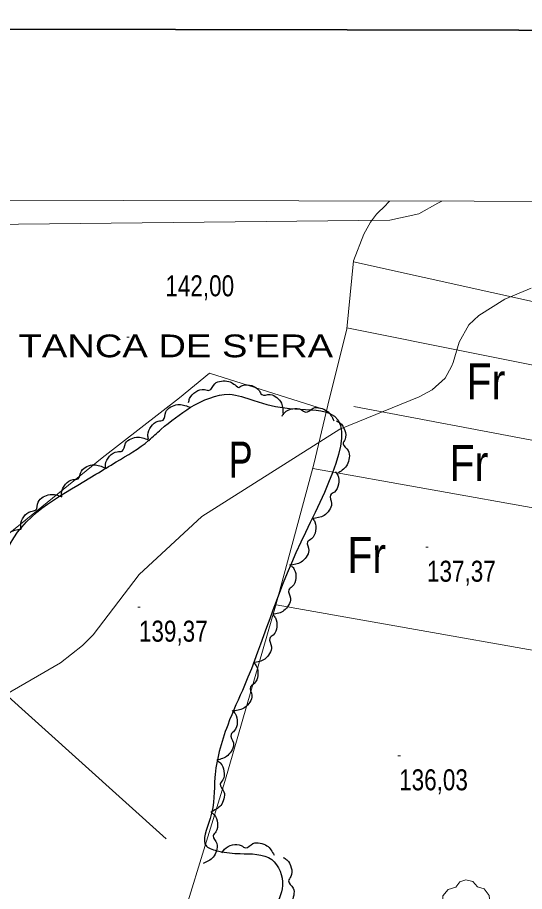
# Model space of a CAD drawing. Extents: x 483843 to 488449, y 4381269 to 4384483.
# Drawn here: x 486538.8 to 486749.9, y 4383843 to 4384207.4 of the extents above; entities that cross this region are included whole.
import ezdxf
from ezdxf.enums import TextEntityAlignment as Align

# ---------------------------------------------------------------- set-up
doc = ezdxf.new("R2010")
doc.units = 0
doc.header["$LTSCALE"] = 3.8
for name, color, linetype, lineweight in [('1', 7, 'Continuous', 13), ('27', 7, 'Continuous', 25), ('29', 7, 'Continuous', 13), ('51', 7, 'Continuous', 13), ('7', 7, 'Continuous', 13), ('9', 7, 'Continuous', 13)]:
    doc.layers.add(name, color=color, linetype=linetype, lineweight=lineweight)
doc.layers.add('31', color=7, linetype='Continuous')
doc.layers.add('5', color=7, linetype='Continuous')

msp = doc.modelspace()

# ---------------------------------------------------------------- linework, layer by layer
at = {"layer": '1', "lineweight": 35}
msp.add_lwpolyline([(484030.2, 4384207.38), (487748.7, 4384200.21), (487743.96, 4381745.22), (484025.46, 4381752.39)], close=True, dxfattribs=at)
at = {"layer": '1'}
msp.add_lwpolyline([(484100.5, 4384135.8), (487678, 4384129), (487674.1, 4381816.7), (484095.6, 4381823.6)], close=True, dxfattribs=at)
at = {"layer": '27'}
for points in [[(486414.83, 4384131.4), (486410.63, 4384110.56), (486406.44, 4384096.14), (486396.1, 4384081.05), (486390.33, 4384071.01), (486383.75, 4384057.44), (486381.94, 4384051.47), (486377.67, 4384040.95), (486369.25, 4384029.81), (486362.27, 4384019.33), (486361.56, 4384011.32), (486364.38, 4383988.31), (486369.26, 4383977.89), (486393.38, 4383964.64), (486411.18, 4383960.63), (486433.64, 4383957.01), (486448.84, 4383949.66), (486458.68, 4383939.99), (486481.86, 4383923.53), (486487.35, 4383919.02), (486494.55, 4383919.07), (486498.18, 4383920.67), (486505.89, 4383925.06), (486507.28, 4383927.51), (486516.61, 4383945.24), (486520.56, 4383953.89), (486532, 4383976.98), (486534.44, 4383985.13), (486535.76, 4383987.96), (486571.44, 4384016.94), (486579.84, 4384022.07), (486593.48, 4384031.1), (486598.5, 4384035.68), (486610.86, 4384044.96)], [(486610.02, 4384046.85), (486610.45, 4384048.57), (486613.04, 4384051.35), (486616.61, 4384052.28), (486618.64, 4384051.96), (486620.93, 4384054.68), (486623.7, 4384055.8), (486626.72, 4384055.67), (486630.85, 4384052.93)], [(486630.93, 4384053.16), (486632.51, 4384053.98), (486636.3, 4384053.91), (486639.37, 4384051.86), (486640.49, 4384050.14), (486644.04, 4384050.24), (486646.73, 4384048.92), (486648.64, 4384046.58), (486649.34, 4384041.68)], [(486610.86, 4384044.96), (486626.92, 4384050.28), (486637.16, 4384047.74), (486652.05, 4384044.37), (486668.53, 4384042.49), (486656.8, 4383988.7), (486633.28, 4383928.86), (486626.29, 4383912.38), (486620.95, 4383890.47), (486618.98, 4383873.39), (486617.47, 4383861.93), (486622.54, 4383859.83), (486631.45, 4383858.8), (486644.63, 4383856.29), (486649.12, 4383845.49), (486645.98, 4383835.48), (486644.53, 4383823.42), (486643.59, 4383804.83), (486644.04, 4383789.06), (486650.17, 4383776.97), (486661.43, 4383767.05), (486666.65, 4383759.32), (486665.61, 4383749.81), (486664.24, 4383748.18), (486659.87, 4383747.12), (486650.35, 4383747.78), (486629.58, 4383749.13), (486612.5, 4383751.02), (486592.66, 4383759.56), (486583.46, 4383745.88), (486580.74, 4383723.11), (486572.16, 4383689.84), (486560.68, 4383659.02), (486553.32, 4383631.81), (486543.18, 4383605.32), (486532.56, 4383576.21), (486523.53, 4383553.45), (486518.77, 4383540.54), (486501.4, 4383543.49), (486476.15, 4383556.3), (486468.29, 4383557.62), (486465.07, 4383557.96), (486462.29, 4383558.08), (486460.26, 4383557.81), (486439.29, 4383544.45), (486415.17, 4383526.49), (486391.53, 4383510.54), (486385.69, 4383506.57), (486377.62, 4383503.39), (486371.16, 4383503.41), (486344.21, 4383501.99), (486329.53, 4383482.99), (486328.89, 4383480.37), (486326.87, 4383475.75), (486312.85, 4383471.45), (486300.33, 4383482.51), (486290.76, 4383490.08), (486283.31, 4383493.56), (486272.61, 4383495.89), (486284, 4383520.94), (486252.05, 4383537.68), (486229.62, 4383543.55), (486216.83, 4383551.46), (486203.95, 4383558.48), (486174.8, 4383524.83), (486205.26, 4383519.21), (486220.9, 4383511.34), (486230.24, 4383508.13), (486241.13, 4383503.92), (486264.65, 4383495.7), (486250.48, 4383465.06), (486236.28, 4383432.55), (486231.27, 4383423.25), (486225.77, 4383410.64), (486214.94, 4383382.73), (486214.23, 4383380.42), (486219.38, 4383373.59), (486258.75, 4383355.69), (486297.13, 4383332.33), (486352.51, 4383306.4), (486336.13, 4383294.48), (486320.46, 4383268.89), (486317.3, 4383262.94), (486310.85, 4383257.93), (486295.11, 4383254.25), (486285.76, 4383251.31), (486282.23, 4383245.35), (486279.78, 4383236.83), (486280.35, 4383218.97), (486309.23, 4383192.29), (486315, 4383181.33)], [(486593.3, 4384031.58), (486593.06, 4384033.34), (486594.42, 4384036.88), (486597.38, 4384039.08), (486599.38, 4384039.55), (486600.48, 4384042.92), (486602.63, 4384045), (486605.48, 4384046), (486610.34, 4384045.01)], [(486648.92, 4384041.16), (486649.94, 4384042.6), (486653.36, 4384044.26), (486657.03, 4384043.83), (486658.81, 4384042.8), (486661.93, 4384044.5), (486664.91, 4384044.54), (486667.68, 4384043.31), (486670.53, 4384039.26)], [(486671.42, 4384039.24), (486672.99, 4384038.41), (486675.09, 4384035.25), (486675.16, 4384031.56), (486674.37, 4384029.66), (486676.48, 4384026.8), (486676.92, 4384023.85), (486676.08, 4384020.94), (486672.45, 4384017.56)], [(486575.49, 4384019.28), (486575.42, 4384021.06), (486577.12, 4384024.45), (486580.29, 4384026.34), (486582.32, 4384026.61), (486583.75, 4384029.87), (486586.09, 4384031.72), (486589.03, 4384032.44), (486593.77, 4384030.97)], [(486557.21, 4384007.59), (486557.12, 4384009.37), (486558.78, 4384012.78), (486561.92, 4384014.71), (486563.96, 4384015.01), (486565.35, 4384018.28), (486567.67, 4384020.16), (486570.6, 4384020.91), (486575.35, 4384019.5)], [(486671.13, 4384018.07), (486672.11, 4384016.59), (486672.42, 4384012.8), (486670.71, 4384009.54), (486669.11, 4384008.25), (486669.58, 4384004.72), (486668.55, 4384001.92), (486666.41, 4383999.78), (486661.6, 4383998.57)], [(486540.36, 4383993.92), (486540.09, 4383995.67), (486541.4, 4383999.23), (486544.33, 4384001.48), (486546.32, 4384001.98), (486547.38, 4384005.37), (486549.49, 4384007.48), (486552.33, 4384008.52), (486557.2, 4384007.6)], [(486661.61, 4383998.56), (486662.59, 4383997.08), (486662.91, 4383993.3), (486661.19, 4383990.03), (486659.59, 4383988.74), (486660.06, 4383985.22), (486659.03, 4383982.42), (486656.9, 4383980.28), (486652.09, 4383979.07)], [(486531.2, 4383974.3), (486530.17, 4383975.75), (486529.76, 4383979.52), (486531.39, 4383982.83), (486532.95, 4383984.16), (486532.38, 4383987.68), (486533.34, 4383990.5), (486535.41, 4383992.7), (486540.18, 4383994.04)], [(486652.92, 4383978.7), (486654.02, 4383977.31), (486654.65, 4383973.57), (486653.21, 4383970.17), (486651.72, 4383968.75), (486652.49, 4383965.28), (486651.69, 4383962.4), (486649.74, 4383960.09), (486645.05, 4383958.48)], [(486645.06, 4383958.47), (486646.15, 4383957.07), (486646.75, 4383953.33), (486645.28, 4383949.94), (486643.78, 4383948.53), (486644.52, 4383945.05), (486643.7, 4383942.18), (486641.73, 4383939.89), (486637.03, 4383938.31)], [(486637.29, 4383938.21), (486638.34, 4383936.78), (486638.84, 4383933.02), (486637.28, 4383929.67), (486635.75, 4383928.3), (486636.39, 4383924.81), (486635.5, 4383921.96), (486633.47, 4383919.72), (486628.73, 4383918.27)], [(486628.17, 4383918.47), (486629.37, 4383917.16), (486630.26, 4383913.47), (486629.06, 4383909.98), (486627.68, 4383908.46), (486628.69, 4383905.05), (486628.1, 4383902.12), (486626.31, 4383899.68), (486621.75, 4383897.74)], [(486621.8, 4383897.69), (486623.21, 4383896.61), (486624.76, 4383893.15), (486624.22, 4383889.5), (486623.14, 4383887.75), (486624.75, 4383884.58), (486624.7, 4383881.6), (486623.39, 4383878.87), (486619.25, 4383876.14)], [(486619.22, 4383876.15), (486620.6, 4383875.03), (486622.04, 4383871.52), (486621.39, 4383867.89), (486620.26, 4383866.18), (486621.77, 4383862.96), (486621.63, 4383859.98), (486620.24, 4383857.29), (486616.02, 4383854.68)], [(486623.97, 4383859.14), (486624.94, 4383860.63), (486628.28, 4383862.42), (486631.96, 4383862.14), (486633.78, 4383861.19), (486636.83, 4383863.02), (486639.81, 4383863.19), (486642.62, 4383862.08), (486645.65, 4383858.15)], [(486649.41, 4383857.19), (486650.91, 4383856.25), (486652.77, 4383852.94), (486652.57, 4383849.26), (486651.66, 4383847.42), (486653.56, 4383844.41), (486653.78, 4383841.44), (486652.73, 4383838.6), (486648.87, 4383835.5)]]:
    msp.add_spline(points, degree=3, dxfattribs=at)
at = {"layer": '29'}
msp.add_lwpolyline([(486723.1, 4383828.45), (486718.56, 4383830.57), (486717.15, 4383833.11), (486717.25, 4383836.09), (486715.88, 4383838.5), (486715.92, 4383841.25), (486718.08, 4383843.85), (486721.27, 4383844.85), (486722.92, 4383847.04), (486725.49, 4383847.87), (486728.35, 4383847.22), (486730.3, 4383844.95), (486733.11, 4383844.13), (486735.24, 4383841.28), (486735.48, 4383838.15), (486733.6, 4383835), (486733.6, 4383832.32), (486731.78, 4383829.71), (486728.16, 4383828.37), (486725.39, 4383829)], close=True, dxfattribs=at)
at = {"layer": '51'}
for p, q in [((486692.86, 4384130), (486693.65, 4384130.87)), ((486777.25, 4384026.52), (486678.77, 4384045.26)), ((486661.73, 4384019.38), (486782.25, 4383997.77)), ((486503.29, 4383952.63), (486600.7, 4383864.95))]:
    msp.add_line(p, q, dxfattribs=at)
for points in [[(486475.09, 4383409.02), (486501.13, 4383482.33), (486547.72, 4383628.44), (486566.43, 4383688.35), (486608.69, 4383835.57), (486625.06, 4383888.83), (486646.53, 4383962.89), (486662.22, 4384021.19), (486667.98, 4384045.79), (486675.93, 4384077.57), (486678.67, 4384105.97), (486682.95, 4384117.09), (486685.73, 4384122), (486688.32, 4384125.34), (486692.13, 4384129.19), (486692.86, 4384130)], [(486678.63, 4384105.56), (486765.73, 4384086.26), (486917.53, 4384056.28)], [(486871.12, 4384065.46), (486865.8, 4384037.48), (486781.81, 4384056.77), (486675.97, 4384077.94)], [(486666.67, 4384043.94), (486666.67, 4384043.94), (486618.72, 4384059.03), (486606.26, 4384048.86), (486574.09, 4384023.8), (486528.03, 4383986.55)], [(486888.86, 4383917.77), (486814.25, 4383932.72), (486646.43, 4383962.56)]]:
    msp.add_lwpolyline(points, dxfattribs=at)
at = {"layer": '7'}
for p, q in [((486584.29, 4384074.15), (486585.29, 4384074.15)), ((486708.8, 4383986.52), (486709.8, 4383986.52)), ((486588.83, 4383961.53), (486589.83, 4383961.53)), ((486697.2, 4383899.57), (486698.2, 4383899.57))]:
    msp.add_line(p, q, dxfattribs=at)
at = {"layer": '9'}
for points in [[(486715.47, 4384130.83), (486715.15, 4384130.73), (486714.05, 4384130.11), (486713.78, 4384130.02), (486705.92, 4384125.5), (486693.87, 4384122.87), (486526.15, 4384121.02), (486504.66, 4384119.49), (486459.32, 4384106.92), (486413.15, 4384102.04), (486410.71, 4384101.28), (486408.74, 4384099.5), (486408.27, 4384098.74), (486407.84, 4384097.85), (486404.79, 4384087.24), (486398.47, 4384073.37), (486397.9, 4384072.47)], [(486529.48, 4383922.58), (486556.66, 4383938.3), (486565.9, 4383945.54), (486570.29, 4383950.02), (486589.44, 4383975.15), (486615.58, 4383999.39), (486672.94, 4384035.79), (486706, 4384049.25), (486711.4, 4384052.19), (486716.92, 4384056.95), (486719.51, 4384061.94), (486720.15, 4384063.53), (486722.74, 4384072.03), (486726.72, 4384079.28), (486730.84, 4384083.15), (486741.7, 4384089.89), (486752.68, 4384094.52)]]:
    msp.add_lwpolyline(points, dxfattribs=at)

# ---------------------------------------------------------------- texts
at = {"layer": '31'}
for s, width, p in [('Fr', 0.85, (486733.83, 4384048.2)), ('P', 0.75, (486631.68, 4384015.55)), ('Fr', 0.85, (486726.74, 4384014.13)), ('Fr', 0.85, (486684.17, 4383975.81))]:
    msp.add_text(s, height=15, dxfattribs=dict(at, width=width)).set_placement(p, align=Align.CENTER)
at = {"layer": '5', "width": 1.25}
msp.add_text("TANCA DE S'ERA", height=9.5, dxfattribs=at).set_placement((486670.19, 4384065.72), align=Align.RIGHT)
at = {"layer": '7', "width": 0.8}
for s, p in [('142,00', (486600.35, 4384091.14)), ('137,37', (486709.3, 4383972.15)), ('139,37', (486589.33, 4383947.16)), ('136,03', (486697.7, 4383885.2))]:
    msp.add_text(s, height=8.75, dxfattribs=at).set_placement(p)

doc.saveas('drawing.dxf')
